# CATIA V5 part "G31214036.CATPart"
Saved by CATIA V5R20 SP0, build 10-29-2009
Part number: G31214036
Revision: 6
Definition: design
Nomenclature: G31214036
Source: made
Description: NOT SPECIFIED
Bounding box of the stored display mesh (mm): x -6 to 36, y -12.31 to 12.31, z -12.5 to 12.5
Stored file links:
  C:\Users\Raffaele\Desktop\3D X SITO CF\BOLEX\23-BUSH REF 312\G31214036.CATPart

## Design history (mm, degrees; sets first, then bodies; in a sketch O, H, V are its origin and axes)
Body1 "MANIFOLD_SOLID_BREP #10203" (main body)
  Solid1: solid without history
Body2 "MANIFOLD_SOLID_BREP #10346"
  Solid2: solid without history
Body3 "MANIFOLD_SOLID_BREP #10489"
  Solid3: solid without history
Body4 "MANIFOLD_SOLID_BREP #10632"
  Solid4: solid without history
Body5 "MANIFOLD_SOLID_BREP #10775"
  Solid5: solid without history
Body6 "MANIFOLD_SOLID_BREP #10920"
  Solid6: solid without history
Body7 "MANIFOLD_SOLID_BREP #11065"
  Solid7: solid without history
Body8 "MANIFOLD_SOLID_BREP #11210"
  Solid8: solid without history
Body9 "MANIFOLD_SOLID_BREP #11355"
  Solid9: solid without history
Body10 "MANIFOLD_SOLID_BREP #11500"
  Solid10: solid without history
Body11 "MANIFOLD_SOLID_BREP #11645"
  Solid11: solid without history
Body12 "MANIFOLD_SOLID_BREP #11790"
  Solid12: solid without history
Body13 "MANIFOLD_SOLID_BREP #11935"
  Solid13: solid without history
Body14 "MANIFOLD_SOLID_BREP #12080"
  Solid14: solid without history
Body15 "MANIFOLD_SOLID_BREP #12225"
  Solid15: solid without history
Body16 "MANIFOLD_SOLID_BREP #12370"
  Solid16: solid without history
Body17 "MANIFOLD_SOLID_BREP #12515"
  Solid17: solid without history
Body18 "MANIFOLD_SOLID_BREP #12660"
  Solid18: solid without history
Body19 "MANIFOLD_SOLID_BREP #12805"
  Solid19: solid without history
Body20 "MANIFOLD_SOLID_BREP #12950"
  Solid20: solid without history
Body21 "MANIFOLD_SOLID_BREP #13095"
  Solid21: solid without history
Body22 "MANIFOLD_SOLID_BREP #13240"
  Solid22: solid without history
Body23 "MANIFOLD_SOLID_BREP #13385"
  Solid23: solid without history
Body24 "MANIFOLD_SOLID_BREP #13530"
  Solid24: solid without history
Body25 "MANIFOLD_SOLID_BREP #13675"
  Solid25: solid without history
Body26 "MANIFOLD_SOLID_BREP #13820"
  Solid26: solid without history
Body27 "MANIFOLD_SOLID_BREP #13965"
  Solid27: solid without history
Body28 "MANIFOLD_SOLID_BREP #14110"
  Solid28: solid without history
Body29 "MANIFOLD_SOLID_BREP #14255"
  Solid29: solid without history
Body30 "MANIFOLD_SOLID_BREP #14400"
  Solid30: solid without history
Body31 "MANIFOLD_SOLID_BREP #14545"
  Solid31: solid without history
Body32 "MANIFOLD_SOLID_BREP #14688"
  Solid32: solid without history
Body33 "MANIFOLD_SOLID_BREP #14831"
  Solid33: solid without history
Body34 "MANIFOLD_SOLID_BREP #14976"
  Solid34: solid without history
Body35 "MANIFOLD_SOLID_BREP #15121"
  Solid35: solid without history
Body36 "MANIFOLD_SOLID_BREP #15266"
  Solid36: solid without history
Body37 "MANIFOLD_SOLID_BREP #15411"
  Solid37: solid without history
Body38 "MANIFOLD_SOLID_BREP #15556"
  Solid38: solid without history
Body39 "MANIFOLD_SOLID_BREP #15701"
  Solid39: solid without history
Body40 "MANIFOLD_SOLID_BREP #15846"
  Solid40: solid without history
Body41 "MANIFOLD_SOLID_BREP #15991"
  Solid41: solid without history
Body42 "MANIFOLD_SOLID_BREP #16136"
  Solid42: solid without history
Body43 "MANIFOLD_SOLID_BREP #16281"
  Solid43: solid without history
Body44 "MANIFOLD_SOLID_BREP #16426"
  Solid44: solid without history
Body45 "MANIFOLD_SOLID_BREP #16571"
  Solid45: solid without history
Body46 "MANIFOLD_SOLID_BREP #16716"
  Solid46: solid without history
Body47 "MANIFOLD_SOLID_BREP #16861"
  Solid47: solid without history
Body48 "MANIFOLD_SOLID_BREP #17006"
  Solid48: solid without history
Body49 "MANIFOLD_SOLID_BREP #17151"
  Solid49: solid without history
Body50 "MANIFOLD_SOLID_BREP #17296"
  Solid50: solid without history
Body51 "MANIFOLD_SOLID_BREP #17441"
  Solid51: solid without history
Body52 "MANIFOLD_SOLID_BREP #17586"
  Solid52: solid without history
Body53 "MANIFOLD_SOLID_BREP #17731"
  Solid53: solid without history
Body54 "MANIFOLD_SOLID_BREP #17876"
  Solid54: solid without history
Body55 "MANIFOLD_SOLID_BREP #18021"
  Solid55: solid without history
Body56 "MANIFOLD_SOLID_BREP #18164"
  Solid56: solid without history
Body57 "MANIFOLD_SOLID_BREP #18307"
  Solid57: solid without history
Body58 "MANIFOLD_SOLID_BREP #18452"
  Solid58: solid without history
Body59 "MANIFOLD_SOLID_BREP #18597"
  Solid59: solid without history
Body60 "MANIFOLD_SOLID_BREP #18742"
  Solid60: solid without history
Body61 "MANIFOLD_SOLID_BREP #18887"
  Solid61: solid without history
Body62 "MANIFOLD_SOLID_BREP #19032"
  Solid62: solid without history
Body63 "MANIFOLD_SOLID_BREP #19177"
  Solid63: solid without history
Body64 "MANIFOLD_SOLID_BREP #19320"
  Solid64: solid without history
Body65 "MANIFOLD_SOLID_BREP #19463"
  Solid65: solid without history
Body66 "MANIFOLD_SOLID_BREP #19608"
  Solid66: solid without history
Body67 "MANIFOLD_SOLID_BREP #19753"
  Solid67: solid without history
Body68 "MANIFOLD_SOLID_BREP #19898"
  Solid68: solid without history
Body69 "MANIFOLD_SOLID_BREP #20043"
  Solid69: solid without history
Body70 "MANIFOLD_SOLID_BREP #20188"
  Solid70: solid without history
Body71 "MANIFOLD_SOLID_BREP #20333"
  Solid71: solid without history
Body72 "MANIFOLD_SOLID_BREP #20478"
  Solid72: solid without history
Body73 "MANIFOLD_SOLID_BREP #20623"
  Solid73: solid without history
